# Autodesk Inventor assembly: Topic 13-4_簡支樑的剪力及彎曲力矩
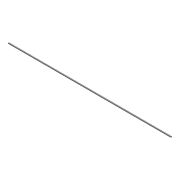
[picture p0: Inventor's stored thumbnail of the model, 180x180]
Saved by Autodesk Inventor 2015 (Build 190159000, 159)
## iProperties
Created: 2020-03
Part Number: Topic 13-4_簡支樑的剪力及彎曲力矩
Document SubType Name: Assembly
Designer: 徐冠倫
Mass: 12110.5 g
Surface Area: 10291.1 cm^2
Volume: 1542.74 cm^3
Density: 7.85 g/cm^3
_SolveAssemblyDoc: Frame Generator Solve Assembly
_Version: 15.0.0
Author: 徐冠倫
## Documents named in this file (3)
- C:\Users\徐冠倫\Desktop\Topic 12-4_簡支樑的剪力及彎曲力矩\Topic 12-4_簡支樑的剪力及彎曲力矩.iam
- C:\Users\徐冠倫\Desktop\Topic 12-4_簡支樑的剪力及彎曲力矩\Topic 12-4_簡支樑的剪力及彎曲力矩.ipt
- C:\Users\徐冠倫\Desktop\Topic 12-4_簡支樑的剪力及彎曲力矩\Topic 12-4_簡支樑的剪力及彎曲力矩\Frame\Frame0001.iam
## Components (2 placed, 2 different names)
1. Topic 12-4_簡支樑的剪力及彎曲力矩:1
2. Frame0001:1 [sub-assembly]
